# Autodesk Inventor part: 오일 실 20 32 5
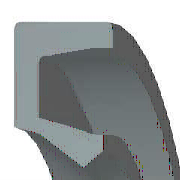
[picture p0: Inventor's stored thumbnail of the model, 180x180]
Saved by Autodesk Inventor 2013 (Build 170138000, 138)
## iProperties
IsCustomPart: 1
Created: 2012-02
Part Number: 오일 실 20 32 5
Material: 고무
Description: 오일 실 - 비스프링, 금속 케이스 GM
Document SubType Name: Modeling
Standard: JIS B 2402
Designer: mdu-01
Standards Organization: JIS
Language: ko-KR
Size Designation: 20 32 5 A
Categories: <MemberInstance><Categories><Category DisplayName="샤프트 부품" InternalName="7f7aeb1f-a693-4053-b835-cee3144e0d98" Mnemonic="SHFT"><Category DisplayName="실링" Intern
Density: 0.93 g/cm^3
Author: mdu-01
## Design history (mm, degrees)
body "Solid1"
revolve "회전1" stored, may be unused: angle "d27" = 360 deg
fillet "모깎기1" dims "d28" = 0.25 (= 0.05 x b)
chamfer "모따기1" distance "d29" = 0.07143 (= 0.0142857 x b); stored, may be unused: second distance "d30" = 0.25 (= 0.05 x b), angle "d35" = 45 deg
sketch "스케치2"
  geometry: L1 (-10.8, -3.238)-(-11.6, -3.863); L2 (-10, -1.625)-(-10.8, -3.238); L3 (-10.6, -1)-(-10, -1.625); L4 (-12.6, -3.75)-(-10.6, -1); L5 (-14.175, -3.75)-(-12.6, -3.75); L6 (-15.375, -1.25)-(-14.175, -3.75); L7 (-15.375, 0)-(-15.375, -1.25); L8 (-16, 0)-(-15.375, 0); L9 (-16, -5)-(-16, 0); L10 (-12.427, -5)-(-16, -5); L11 (-11.6, -3.863)-(-12.427, -5); L12 (0, -9.6)-(0, 1.6) reference; L13 (-14, 0)-(-28, 0) reference
  constraints: 22 end point, 3 horizontal, 2 vertical, 1 parallel
  dimensions: "d2" = 5 distance of L9.start L8.start (= b); "d4" = 1 vertical distance of L8.start L3.start (= 0.2 x b); "d6" = 0.625 distance of L8.start L7.start (= 0.125 x b); "d8" = 1.25 distance of L7.start L6.start (= 0.25 x b); "d10" = 1.25 vertical distance of L5.start L9.start (= 0.25 x b); "d12" = 1.2 horizontal distance of L6.start L5.start (= 0.1 x dd - 0.1 x Diam); "d14" = 1.6129 vertical distance of L2.start L1.start (= 0.322581 x b); "d16" = 0.8 horizontal distance of L1.start L1.end (= 0.0666667 x dd - 0.0666667 x Diam); "d18" = 0.8 horizontal distance of L2.start L1.start (= 0.0666667 x dd - 0.0666667 x Diam); "d20" = 0.625 vertical distance of L3.start L2.start (= 0.125 x b); "d22" = 0.6 horizontal distance of L3.start L2.start (= 0.05 x dd - 0.05 x Diam); "d24" = 0.625 vertical distance of L1.start L1.end (= 0.125 x b); "d26" = 2 horizontal distance of L4.start L3.start (= 0.166667 x dd - 0.166667 x Diam); "d31" = 0 distance between parallel lines of L8 L13; "d32" = 16 distance between parallel lines of L12 L9 (= 0.5 x dd); "d33" = 10 distance from line of L12 L2.start (= 0.5 x Diam)
other parameters: "dd" = 32 [user parameter; used in 6 equation terms], "b" = 5 [user parameter; used in 11 equation terms], "d1" = 8 (derived), "d3" = 1.6 (derived), "d5" = 1 (derived), "d7" = 2 (derived), "d9" = 2 (derived), "d11" = 2 (derived), "d13" = 2.58065 (derived), "d15" = 1.33333 (derived), "d17" = 1.33333 (derived), "d19" = 1 (derived), "d21" = 1 (derived), "d23" = 1 (derived), "d25" = 3.33333 (derived), "d34" = 0
